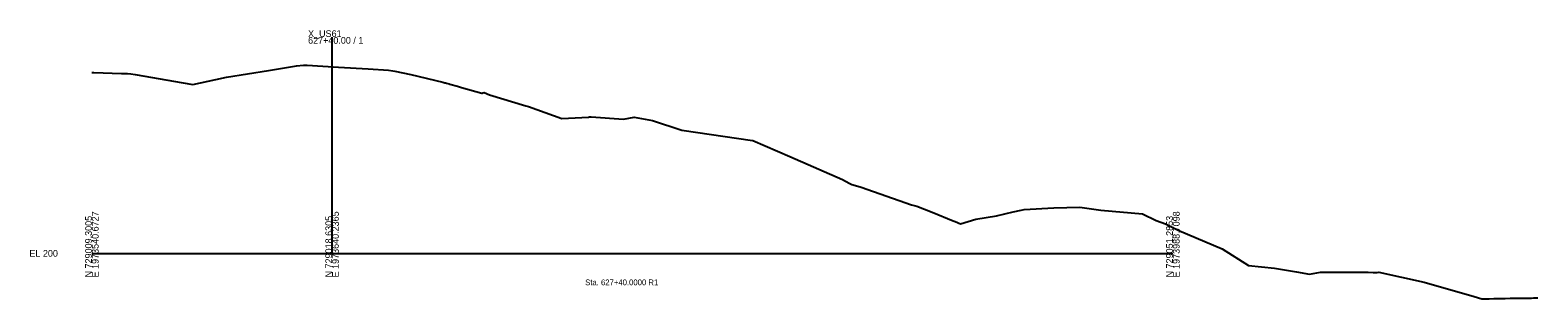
# Model space of a CAD drawing. Extents: x -26 to 630, y -39 to 9098.
# Drawn here: x -26 to 602, y 8481 to 8593 of the extents above; entities that cross this region are included whole.
import ezdxf

# ---------------------------------------------------------------- set-up
doc = ezdxf.new("R2010")
doc.units = 0
for name, color, linetype in [('Draft_XS_Grid', 7, 'Continuous'), ('Draft_XS_Text', 7, 'Continuous'), ('DTM_X_GROUND', 7, 'Continuous'), ('XS_CELL', 7, 'Continuous')]:
    doc.layers.add(name, color=color, linetype=linetype)

msp = doc.modelspace()

# ---------------------------------------------------------------- linework, layer by layer
at = {"layer": 'DTM_X_GROUND'}
msp.add_lwpolyline([(0, 8575.22), (0.79, 8575.23), (12.36, 8574.85), (14.87, 8574.77), (16.17, 8574.64), (18.01, 8574.44), (37.98, 8570.98), (41.97, 8570.29), (51.55, 8572.35), (55.99, 8573.34), (73.57, 8576.1), (85.2, 8578.02), (88.05, 8578.23), (88.73, 8578.27), (89.62, 8578.23), (102.73, 8577.52), (115.05, 8576.7), (123.46, 8576.15), (125.26, 8575.88), (126.05, 8575.76), (132.73, 8574.42), (146.06, 8571.21), (146.93, 8570.99), (147.22, 8570.95), (147.58, 8570.8), (148.73, 8570.48), (148.98, 8570.41), (152.16, 8569.52), (153.93, 8569.02), (162.29, 8566.65), (162.52, 8566.71), (162.68, 8566.75), (163.3, 8566.87), (165.58, 8565.98), (180.7, 8561.35), (181.22, 8561.2), (181.78, 8561.03), (195.59, 8556.04), (206.7, 8556.69), (207.11, 8556.73), (207.88, 8556.73), (221.24, 8555.8), (225.78, 8556.68), (233.4, 8555.29), (245.63, 8551.29), (274.96, 8546.98), (275.06, 8546.94), (275.1, 8546.93), (275.18, 8546.93), (290.58, 8540.35), (312.48, 8530.71), (315.22, 8529.16), (316.06, 8528.79), (316.36, 8528.66), (317.9, 8528.22), (320.22, 8527.55), (341.2, 8520.2), (343.47, 8519.66), (349.83, 8517.11), (358.54, 8513.6), (359.4, 8513.26), (361.57, 8512.28), (367.91, 8514.26), (376.63, 8515.69), (383.51, 8517.25), (386.88, 8518.01), (388.16, 8518.3), (400.5, 8518.93), (411.23, 8519.25), (419.97, 8517.91), (437.42, 8516.39), (443.01, 8513.73), (446.93, 8512.32), (452.51, 8509.59), (470.52, 8501.96), (481.5, 8494.96), (492.29, 8493.92), (501.48, 8492.34), (506.93, 8491.32), (511.42, 8492.21), (515.86, 8492.18), (531.23, 8492.19), (533.31, 8492.01), (535.07, 8492.07), (535.77, 8492.16), (554.55, 8488.02), (575.48, 8482.13), (578.58, 8481.1), (581.69, 8481.16), (583.56, 8481.2), (586.2, 8481.24), (588.39, 8481.29), (590.44, 8481.32), (592.59, 8481.34), (595.56, 8481.39), (597.72, 8481.42), (599.26, 8481.43), (600.06, 8481.46), (600.7, 8481.49), (601.23, 8481.51), (601.48, 8481.52), (601.65, 8481.53), (601.8, 8481.55), (601.92, 8481.56)], dxfattribs=at)
at = {"layer": 'XS_CELL'}
for p, q in [((100, 8500), (100, 8590)), ((0, 8500), (100, 8500)), ((100, 8500), (450, 8500))]:
    msp.add_line(p, q, dxfattribs=at)

# ---------------------------------------------------------------- texts
at = {"layer": 'Draft_XS_Grid'}
msp.add_text('-', height=0.0001, dxfattribs=at).set_placement((0, 8500))
at = {"layer": 'Draft_XS_Text'}
msp.add_text('Sta. 627+40.0000 R1', height=2.4, dxfattribs=at).set_placement((205.34, 8486.75))
at = {"layer": 'XS_CELL'}
for s, p in [('X_US61', (90, 8590)), ('627+40.00 / 1', (90, 8587.2)), ('EL 200', (-26, 8498.6))]:
    msp.add_text(s, height=2.8, dxfattribs=at).set_placement(p)
for s, p in [('E 1973540.6727', (2.8, 8490)), ('E 1973640.2365', (102.8, 8490)), ('E 1973988.7098', (452.8, 8490)), ('N 729009.3005', (0, 8490)), ('N 729018.6305', (100, 8490)), ('N 729051.2853', (450, 8490))]:
    msp.add_text(s, height=2.8, rotation=90, dxfattribs=at).set_placement(p)

doc.saveas('drawing.dxf')
